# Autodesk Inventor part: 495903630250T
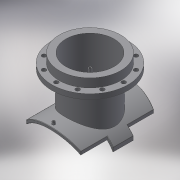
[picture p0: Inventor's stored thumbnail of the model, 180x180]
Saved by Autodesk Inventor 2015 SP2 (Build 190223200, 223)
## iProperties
Created: 2017-10
Part Number: 495903630250T
Material: Generic
Description: PLASSON FLANGED BRANCH SADDLE 560-630X250
Document SubType Name: Modeling
Designer: KIM
Mass: 6011.41 g
Surface Area: 9093.19 cm^2
Volume: 6011.41 cm^3
Density: 1 g/cm^3
Appearance: Default
Author: KIM
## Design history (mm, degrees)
derived "495904.ipt"
feature "Solid1::495904.ipt"
feature "Solid2::495904.ipt"
tag "TaggingFeature1"
body "Solid1"
other parameters: "d1" = 15, "d4" = 0, "d6" = 105, "d7" = 0, "d11" = 3.15, "d12" = 340.6, "d13" = 14, "d14" = 189, "d16" = 5 deg, "d18" = 4, "d19" = 14, "d20" = 0, "d21" = 3, "d22" = 0, "d23" = 555, "d36" = 189, "d38" = 0, "d39" = 2, "d40" = 225, "d43" = 395, "d46" = 256, "d47" = 16, "d48" = 10.4, "d49" = 157.5, "d51" = 642.6, "d53" = 0, "d54" = 22, "d55" = 175, "d57" = 0, "d59" = 360 deg, "d61" = 26, "d63" = 0, "H_" = 225, "x_" = 15, "D_" = 16, "D_1" = 395, "t_" = 26, "s_" = 22
